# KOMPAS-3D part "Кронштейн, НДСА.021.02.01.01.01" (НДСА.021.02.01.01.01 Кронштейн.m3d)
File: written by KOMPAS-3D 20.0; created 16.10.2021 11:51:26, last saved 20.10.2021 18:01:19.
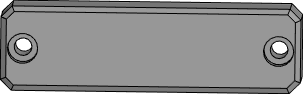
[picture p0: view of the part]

Document properties: Автор: adminzsc; Полное имя файла: C:\Users\vasilyeva\Desktop\PM_APPIUS\НДСА.021.02.01.01.01 Кронштейн.m3d

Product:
- Part/product: Кронштейн  | designation НДСА.021.02.01.01.01
    Материал: АМг6  ГОСТ 4784-2019 (density 2640 kg/m3)
    Масса: 0.568658
    additional columns: <item xmlns="http://appius.ru/pdm" xmlns:xs="http://www.w3.org/2001/XMLSchema" x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; <item xmlns="http://appius.ru/pdm" xmlns:xs="http://www.w3.org/2001/XMLSchema" x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; <item xmlns="http://appius.ru/pdm" xmlns:xs="http://www.w3.org/2001/XMLSchema" x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
    source file: НДСА.021.02.01.01.01 Кронштейн.cdw

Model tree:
1. Эскиз:1
2. Элемент выдавливания:1
     Расстояние 1 = 31
3. Эскиз:2  (with: Элемент выдавливания:1)
4. Элемент выдавливания:2
     Расстояние 2 = 50
5. Эскиз:3  (with: Элемент выдавливания:1)
6. Элемент выдавливания:3
     Расстояние 2 = 20.5
7. Эскиз:4  (with: Элемент выдавливания:1)
8. Эскиз:6  (with: Элемент выдавливания:1)
9. Смещенная плоскость:1  (with: Элемент выдавливания:1)
     Расстояние = -32.59
10. Эскиз:9  (with: Элемент выдавливания:1)
11. Эскиз:11
12. Элемент по траектории:1
     Толщина стенки 1 = 1
13. Смещенная плоскость:2  (with: Элемент выдавливания:1)
     Расстояние = -76.5
14. Эскиз:12
15. Элемент по траектории:3
16. Эскиз:13  (with: Элемент выдавливания:1)
17. Элемент выдавливания:6
     Расстояние 2 = 3
18. Эскиз:14  (with: Элемент выдавливания:1)
19. Отверстие:1  (with: Элемент выдавливания:1)  (labels: BSF 3/16'')
     Глубина выреза = 10; Диаметр отверстия = 3.74616; Угол конуса дна = 118; Расстояние 2 = 25.4
20. BSF 3/16''  (with: Элемент выдавливания:1)  (labels: cil5_ex_DIN 477 BSF fine)
     Длина резьбы = 8; Шаг резьбы = 0.794; Номинальный диаметр резьбы = 4.763
21. Отверстие:2  (with: Элемент выдавливания:1, BSF 3/16'')  (labels: BSF 3/16''; cil5_ex_DIN 477 BSF fine)
     Глубина выреза = 10; Диаметр отверстия = 3.74616; Угол конуса дна = 118; Расстояние 1 = 86; Расстояние 2 = 8.94552; Длина резьбы = 8; Шаг резьбы = 0.794; Номинальный диаметр резьбы = 4.763
22. Отверстие:3  (with: Элемент выдавливания:1, BSF 3/16'')  (labels: BSF 3/16''; cil5_ex_DIN 477 BSF fine)
     Глубина выреза = 10; Диаметр отверстия = 3.74616; Угол конуса дна = 118; Расстояние 1 = 67; Расстояние 2 = 8.94552; Длина резьбы = 8; Шаг резьбы = 0.794; Номинальный диаметр резьбы = 4.763
23. Отверстие:4  (with: Элемент выдавливания:1, BSF 3/16'')  (labels: BSF 3/16''; cil5_ex_DIN 477 BSF fine)
     Глубина выреза = 10; Диаметр отверстия = 3.74616; Угол конуса дна = 118; Расстояние 1 = 86; Расстояние 2 = 41.8545; Длина резьбы = 8; Шаг резьбы = 0.794; Номинальный диаметр резьбы = 4.763
24. Отверстие:5  (with: Элемент выдавливания:1, BSF 3/16'')  (labels: BSF 3/16''; cil5_ex_DIN 477 BSF fine)
     Глубина выреза = 10; Диаметр отверстия = 3.74616; Угол конуса дна = 118; Расстояние 1 = 67; Расстояние 2 = 41.8545; Длина резьбы = 8; Шаг резьбы = 0.794; Номинальный диаметр резьбы = 4.763
25. Отверстие:6  (with: Элемент выдавливания:1, BSF 3/16'')  (labels: BSF 3/16''; cil5_ex_DIN 477 BSF fine)
     Глубина выреза = 10; Диаметр отверстия = 3.74616; Угол конуса дна = 118; Расстояние 1 = 42; Расстояние 2 = 41.8545; Длина резьбы = 8; Шаг резьбы = 0.794; Номинальный диаметр резьбы = 4.763
26. Отверстие:7  (with: Элемент выдавливания:1, BSF 3/16'')  (labels: BSF 3/16''; cil5_ex_DIN 477 BSF fine)
     Глубина выреза = 10; Диаметр отверстия = 3.74616; Угол конуса дна = 118; Расстояние 1 = 23; Расстояние 2 = 41.8545; Длина резьбы = 8; Шаг резьбы = 0.794; Номинальный диаметр резьбы = 4.763
27. Отверстие:8  (with: Элемент выдавливания:1, BSF 3/16'')  (labels: BSF 3/16''; cil5_ex_DIN 477 BSF fine)
     Глубина выреза = 10; Диаметр отверстия = 3.74616; Угол конуса дна = 118; Расстояние 1 = 13.5; Расстояние 2 = 25.4; Длина резьбы = 8; Шаг резьбы = 0.794; Номинальный диаметр резьбы = 4.763
28. Отверстие:9  (with: Элемент выдавливания:1, BSF 3/16'')  (labels: BSF 3/16''; cil5_ex_DIN 477 BSF fine)
     Глубина выреза = 10; Диаметр отверстия = 3.74616; Угол конуса дна = 118; Расстояние 1 = 23; Расстояние 2 = 8.94552; Длина резьбы = 8; Шаг резьбы = 0.794; Номинальный диаметр резьбы = 4.763
29. Отверстие:10  (with: Элемент выдавливания:1, BSF 3/16'')  (labels: BSF 3/16''; cil5_ex_DIN 477 BSF fine)
     Глубина выреза = 10; Диаметр отверстия = 3.74616; Угол конуса дна = 118; Расстояние 1 = 42; Расстояние 2 = 8.94552; Длина резьбы = 8; Шаг резьбы = 0.794; Номинальный диаметр резьбы = 4.763
30. Эскиз:15  (with: Элемент выдавливания:1)
31. Эскиз:16  (with: Элемент выдавливания:1)
32. Отверстие:11  (with: Элемент выдавливания:1)
     Глубина выреза = 70.4; Диаметр отверстия = 6.5; Угол конуса дна = 118; Расстояние 1 = 15.5; Расстояние 2 = -8; Диаметр цековки = 11; Глубина цековки = 20.4
33. Отверстие:12  (with: Элемент выдавливания:1)
     Глубина выреза = 70.4; Диаметр отверстия = 6.5; Угол конуса дна = 118; Расстояние 1 = 15.5; Расстояние 2 = 8; Диаметр цековки = 11; Глубина цековки = 20.4
34. Фаска:5  (with: Элемент выдавливания:1)
     Угол = 45; Длина 1 = 4; Длина 2 = 4
35. Фаска:6  (with: Элемент выдавливания:1, Фаска:5)
     Угол = 45; Длина 1 = 2; Длина 2 = 2
36. Фаска:7  (with: Фаска:5, Элемент выдавливания:1)
     Угол = 45; Длина 1 = 2; Длина 2 = 2
37. Эскиз:17  (with: Элемент выдавливания:1)  (labels: АМг6  ГОСТ 4784-2019)

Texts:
  НДСА.021.02.01.01.01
